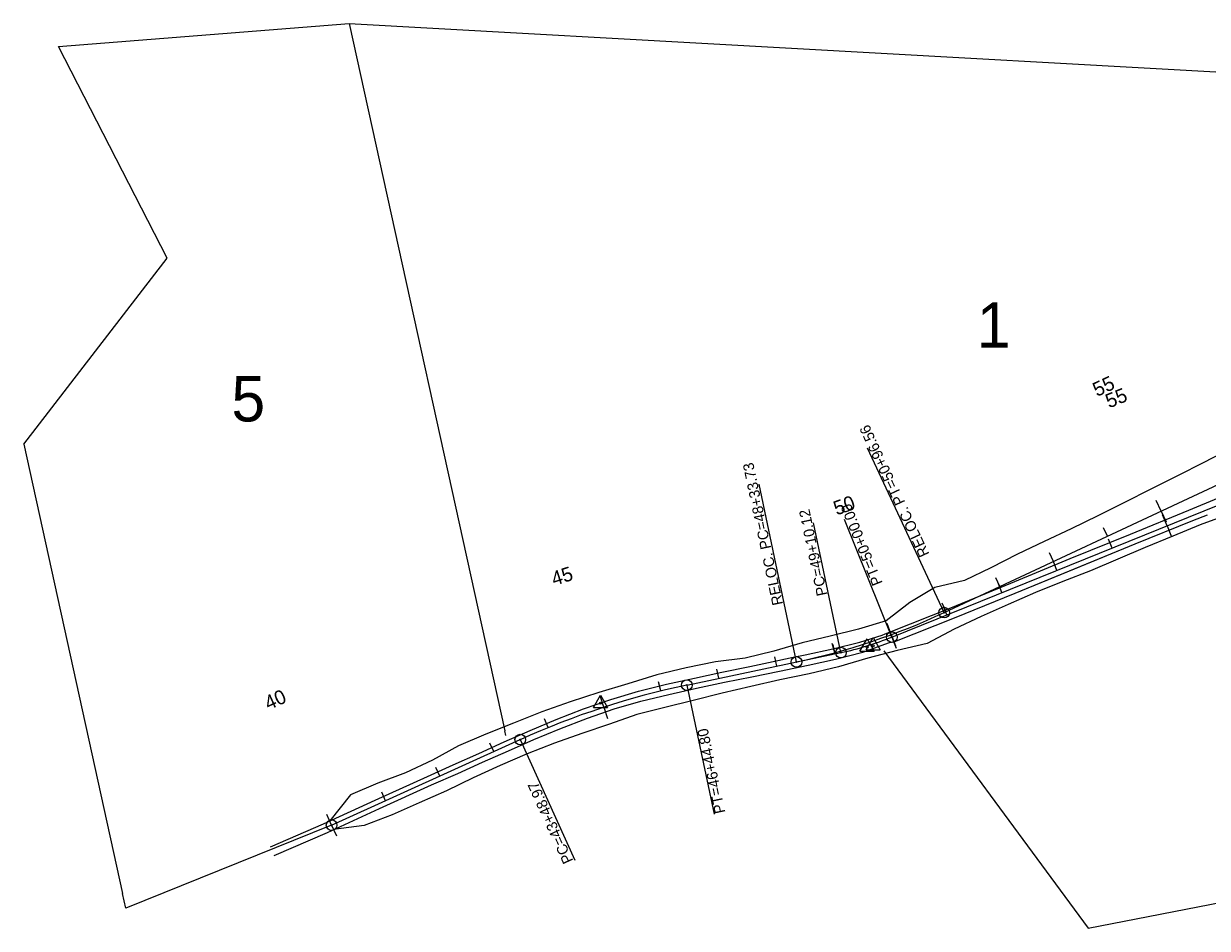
# Model space of a CAD drawing. Extents: x 1965308 to 1970456, y 1116335 to 1119906.
# Drawn here: x 1965308 to 1967302, y 1116957 to 1118481 of the extents above; entities that cross this region are included whole.
import ezdxf

# ---------------------------------------------------------------- set-up
doc = ezdxf.new("R2010")
doc.units = 0
for name, color, linetype in [('RD_EX_DV_Prop', 7, 'Continuous'), ('RD_EX_DV_TX_Prop', 7, 'Continuous'), ('RD_EX_Road', 7, 'Continuous'), ('RD_EX_RW', 7, 'Continuous'), ('RD_HC_Cl', 7, 'Continuous'), ('RD_HC_CL_Rel', 7, 'Continuous'), ('RD_HC_Data', 7, 'Continuous'), ('RD_HC_Data_Rel', 7, 'Continuous'), ('RD_HC_Data_Tic', 7, 'Continuous'), ('RD_HC_Data_Tic_Rel', 7, 'Continuous'), ('RD_HC_TX_Rel_Sta50', 7, 'Continuous'), ('RD_HC_TX_StaOther', 7, 'Continuous'), ('RD_PD_RW', 7, 'Continuous'), ('RD_SMD_Locator', 7, 'Continuous')]:
    doc.layers.add(name, color=color, linetype=linetype)

msp = doc.modelspace()

# ---------------------------------------------------------------- linework, layer by layer
at = {"layer": 'RD_EX_DV_Prop'}
for p, q in [((1965366.5, 1118442.8), (1965856.7, 1118481.4)), ((1965856.7, 1118481.4), (1967851.7, 1118370.2)), ((1965856.7, 1118481.4), (1966118.5, 1117290.2)), ((1965550, 1118086.1), (1965366.5, 1118442.8)), ((1965308.1, 1117773.1), (1965550, 1118086.1)), ((1965308.1, 1117773.1), (1965474.5, 1117016.1)), ((1966757.3, 1117425.1), (1967101.3, 1116957.5)), ((1966120.2, 1117282.5), (1966118.5, 1117290.2)), ((1965826.9, 1117131.2), (1965479.9, 1116991.6)), ((1965479.9, 1116991.6), (1965474.5, 1117016.1)), ((1967101.3, 1116957.5), (1967409.3, 1117017.8))]:
    msp.add_line(p, q, dxfattribs=at)
at = {"layer": 'RD_EX_Road'}
for points in [[(1966769.5, 1117457.5), (1966870.2, 1117497.3), (1966971.2, 1117539), (1967071.1, 1117580.2), (1967172.6, 1117621.5), (1967270.8, 1117661.7), (1967321.1, 1117682.6), (1967371.5, 1117702.9), (1967470.3, 1117741.6), (1967566.7, 1117779.5), (1967661.2, 1117817.5), (1967694.4, 1117831.2)], [(1966775.8, 1117440.6), (1966876.2, 1117480.4), (1966978.5, 1117522.1), (1967078.3, 1117563.1), (1967180.7, 1117605.1), (1967278, 1117644.7), (1967302.2, 1117654.1)], [(1965723.8, 1117094.5), (1965813.3, 1117133.7), (1965900.5, 1117173.5), (1965988.5, 1117213.4), (1966031.8, 1117233), (1966074.7, 1117252.1), (1966117.8, 1117271.6), (1966161.1, 1117290.5), (1966205.4, 1117309.2), (1966251.2, 1117327.4), (1966297.2, 1117343.1), (1966344.1, 1117357), (1966390.8, 1117368.6), (1966438.1, 1117379.1), (1966484.5, 1117389.1), (1966531.2, 1117398.7), (1966578.4, 1117408.6), (1966604.5, 1117414.1), (1966624.5, 1117418.3), (1966671.3, 1117428.3), (1966716.5, 1117439.3), (1966736.6, 1117445.6), (1966754.1, 1117451.4), (1966759.7, 1117453.5), (1966769.5, 1117457.5)], [(1965730, 1117080.3), (1965819.8, 1117119.1), (1965907.7, 1117159.3), (1965995.4, 1117199), (1966039.3, 1117218.5), (1966081.2, 1117237.1), (1966124.7, 1117256.6), (1966167.7, 1117275.6), (1966211.5, 1117293.6), (1966257.8, 1117311.6), (1966302.7, 1117327.2), (1966347.9, 1117340), (1966394.8, 1117351.6), (1966441.6, 1117361.9), (1966488.6, 1117372.1), (1966534.9, 1117381.3), (1966581.2, 1117390.9), (1966629.5, 1117400.9), (1966675.6, 1117411.1), (1966721.7, 1117422.8), (1966766.8, 1117439), (1966775.8, 1117440.6)]]:
    msp.add_lwpolyline(points, dxfattribs=at)
at = {"layer": 'RD_EX_RW'}
for points in [[(1966769.5, 1117457.5), (1966870.2, 1117497.3), (1966971.2, 1117539), (1967071.1, 1117580.2), (1967172.6, 1117621.5), (1967270.8, 1117661.7), (1967321.1, 1117682.6), (1967371.5, 1117702.9), (1967470.3, 1117741.6), (1967566.7, 1117779.5), (1967661.2, 1117817.5), (1967694.6, 1117831.3)], [(1966775.8, 1117440.6), (1966876.2, 1117480.4), (1966978.5, 1117522.1), (1967180.7, 1117605.1), (1967278, 1117644.7), (1967302.2, 1117654.1)], [(1965723.8, 1117094.5), (1965813.3, 1117133.7), (1965900.5, 1117173.5), (1965988.5, 1117213.4), (1966031.8, 1117233), (1966074.7, 1117252.1), (1966117.8, 1117271.6), (1966161.1, 1117290.5), (1966205.4, 1117309.2), (1966251.2, 1117327.4), (1966297.2, 1117343.1), (1966344.1, 1117357), (1966390.8, 1117368.6), (1966438.1, 1117379.1), (1966484.5, 1117389.1), (1966531.2, 1117398.7), (1966578.4, 1117408.6), (1966604.5, 1117414.1), (1966624.5, 1117418.3), (1966671.3, 1117428.3), (1966716.5, 1117439.3), (1966736.6, 1117445.6), (1966754.1, 1117451.4), (1966759.7, 1117453.5), (1966769.5, 1117457.5)], [(1965730, 1117080.3), (1965819.8, 1117119.1), (1965907.7, 1117159.3), (1965995.4, 1117199), (1966039.3, 1117218.5), (1966081.2, 1117237.1), (1966124.7, 1117256.6), (1966167.7, 1117275.6), (1966211.5, 1117293.6), (1966257.8, 1117311.6), (1966302.7, 1117327.2), (1966347.9, 1117340), (1966394.8, 1117351.6), (1966441.6, 1117361.9), (1966488.6, 1117372.1), (1966534.9, 1117381.3), (1966581.2, 1117390.9), (1966629.5, 1117400.9), (1966675.6, 1117411.1), (1966721.7, 1117422.8), (1966766.8, 1117439), (1966775.8, 1117440.6)]]:
    msp.add_lwpolyline(points, dxfattribs=at)
at = {"layer": 'RD_HC_Cl'}
for p, q in [((1966770.7, 1117448.1), (1967849.5, 1117883.9)), ((1966425.3, 1117367.2), (1966684.9, 1117421.9)), ((1965826.9, 1117131.2), (1966144.7, 1117275.3))]:
    msp.add_line(p, q, dxfattribs=at)
for centre, radius, start, end in [((1966579.6, 1117921.3), 510.3, 281.9047, 291.9958), ((1966705.5, 1116038), 1358.4, 101.9047, 114.3826)]:
    msp.add_arc(centre, radius, start, end, dxfattribs=at)
at = {"layer": 'RD_HC_CL_Rel'}
msp.add_line((1966858.9, 1117489.3), (1967685.7, 1117875.7), dxfattribs=at)
msp.add_arc((1966373.7, 1118527.5), 1145.9, 281.9047, 295.0463, dxfattribs=at)
at = {"layer": 'RD_HC_Data'}
for p, q in [((1966684.9, 1117421.9), (1966638.8, 1117640.3)), ((1966770.7, 1117448.1), (1966690.8, 1117646)), ((1966717, 1117424.4), (1966729, 1117445)), ((1966729, 1117445), (1966740.9, 1117424.4)), ((1966717, 1117424.4), (1966740.9, 1117424.4)), ((1966425.3, 1117367.2), (1966471.1, 1117149.9)), ((1966268, 1117329.7), (1966280, 1117350.3)), ((1966280, 1117350.3), (1966291.9, 1117329.7)), ((1966268, 1117329.7), (1966291.9, 1117329.7)), ((1966144.7, 1117275.3), (1966236.8, 1117072.1))]:
    msp.add_line(p, q, dxfattribs=at)
for centre, radius in [((1966770.7, 1117448.1), 9), ((1966770.7, 1117448.1), 9), ((1966684.9, 1117421.9), 9), ((1966729, 1117431.2), 1.59), ((1966770.7, 1117448.1), 0.845), ((1966770.7, 1117448.1), 0.845), ((1966684.9, 1117421.9), 0.845), ((1966425.3, 1117367.2), 9), ((1966425.3, 1117367.2), 0.845), ((1966280, 1117336.6), 1.59), ((1966144.7, 1117275.3), 9), ((1966144.7, 1117275.3), 0.845), ((1965826.9, 1117131.2), 9), ((1965826.9, 1117131.2), 0.845)]:
    msp.add_circle(centre, radius, dxfattribs=at)
at = {"layer": 'RD_HC_Data_Rel'}
for p, q in [((1966858.9, 1117489.3), (1966729.5, 1117766.2)), ((1966610.1, 1117406.2), (1966547, 1117705.5)), ((1966727.4, 1117426.5), (1966739.3, 1117447.2)), ((1966739.3, 1117447.2), (1966751.2, 1117426.5)), ((1966727.4, 1117426.5), (1966751.2, 1117426.5))]:
    msp.add_line(p, q, dxfattribs=at)
for centre, radius in [((1966858.9, 1117489.3), 9), ((1966858.9, 1117489.3), 0.845), ((1966739.3, 1117433.4), 1.59), ((1966610.1, 1117406.2), 9), ((1966610.1, 1117406.2), 0.845)]:
    msp.add_circle(centre, radius, dxfattribs=at)
at = {"layer": 'RD_HC_Data_Tic'}
for p, q in [((1967234.3, 1117635.4), (1967226.9, 1117653.9)), ((1967234.3, 1117635.4), (1967241.8, 1117616.8)), ((1967141.6, 1117597.9), (1967135.6, 1117612.8)), ((1967048.9, 1117560.5), (1967042.9, 1117575.3)), ((1966956.2, 1117523), (1966950.2, 1117537.9)), ((1966863.5, 1117485.6), (1966857.5, 1117500.4)), ((1966770.7, 1117448.1), (1966763.2, 1117466.7)), ((1966675, 1117419.9), (1966671.7, 1117435.5)), ((1966770.7, 1117448.1), (1966778.2, 1117429.6)), ((1966577.1, 1117399.2), (1966573.8, 1117414.9)), ((1966479.3, 1117378.6), (1966476, 1117394.3)), ((1966381.6, 1117357.3), (1966377.8, 1117372.8)), ((1966285.4, 1117329.9), (1966279.3, 1117348.9)), ((1966285.4, 1117329.9), (1966291.6, 1117310.8)), ((1966191.6, 1117295.5), (1966185.5, 1117310.3)), ((1966100.1, 1117255.1), (1966093.5, 1117269.6)), ((1966009, 1117213.8), (1966002.4, 1117228.3)), ((1965917.9, 1117172.5), (1965911.3, 1117187.1)), ((1965826.9, 1117131.2), (1965818.6, 1117149.4)), ((1965826.9, 1117131.2), (1965835.1, 1117113))]:
    msp.add_line(p, q, dxfattribs=at)
at = {"layer": 'RD_HC_Data_Tic_Rel'}
for p, q in [((1967224.4, 1117660.1), (1967215.9, 1117678.2)), ((1967224.4, 1117660.1), (1967232.8, 1117642)), ((1967133.8, 1117617.8), (1967127, 1117632.3)), ((1967043.2, 1117575.4), (1967036.4, 1117589.9)), ((1966952.6, 1117533.1), (1966945.8, 1117547.6)), ((1966862, 1117490.8), (1966855.2, 1117505.2)), ((1966769.8, 1117452.2), (1966762.9, 1117470.9)), ((1966769.8, 1117452.2), (1966776.7, 1117433.4)), ((1966674.5, 1117421.7), (1966670.3, 1117437.2))]:
    msp.add_line(p, q, dxfattribs=at)
at = {"layer": 'RD_PD_RW'}
for p, q in [((1967340.9, 1117765), (1967296.4, 1117742.1)), ((1967296.4, 1117742.1), (1967251.7, 1117719.7)), ((1967251.7, 1117719.7), (1967207.1, 1117697.1)), ((1967207.1, 1117697.1), (1967162.4, 1117674.5)), ((1967162.4, 1117674.5), (1967117.5, 1117652.5)), ((1967117.5, 1117652.5), (1967072.6, 1117630.4)), ((1967337.6, 1117654.3), (1967290.1, 1117637.3)), ((1967072.6, 1117630.4), (1967027.5, 1117609)), ((1967290.1, 1117637.3), (1967243.8, 1117618.3)), ((1967243.8, 1117618.3), (1967197.6, 1117599.1)), ((1967027.5, 1117609), (1966982.2, 1117587.8)), ((1967197.6, 1117599.1), (1967151.6, 1117579.5)), ((1966982.2, 1117587.8), (1966937.7, 1117564.8)), ((1967151.6, 1117579.5), (1967105.6, 1117559.8)), ((1966937.7, 1117564.8), (1966892.8, 1117543.2)), ((1967105.6, 1117559.8), (1967058.8, 1117541.9)), ((1966842.9, 1117531.7), (1966801.1, 1117506.3)), ((1966892.8, 1117543.2), (1966842.9, 1117531.7)), ((1967058.8, 1117541.9), (1967012.5, 1117522.9)), ((1967012.5, 1117522.9), (1966966.7, 1117502.9)), ((1966801.1, 1117506.3), (1966761, 1117475.6)), ((1966966.7, 1117502.9), (1966920.9, 1117482.7)), ((1966761, 1117475.6), (1966714.3, 1117461.6)), ((1966920.9, 1117482.7), (1966875.7, 1117461.6)), ((1966714.3, 1117461.6), (1966666.9, 1117449.8)), ((1966875.7, 1117461.6), (1966830.2, 1117437.3)), ((1966619.5, 1117438.3), (1966571.8, 1117424.1)), ((1966666.9, 1117449.8), (1966619.5, 1117438.3)), ((1966830.2, 1117437.3), (1966779.4, 1117425.6)), ((1966523.3, 1117412.5), (1966473.5, 1117406.2)), ((1966571.8, 1117424.1), (1966523.3, 1117412.5)), ((1966730, 1117412.4), (1966680.9, 1117398.2)), ((1966779.4, 1117425.6), (1966730, 1117412.4)), ((1966424.4, 1117396.5), (1966374.9, 1117384.3)), ((1966473.5, 1117406.2), (1966424.4, 1117396.5)), ((1966680.9, 1117398.2), (1966631.4, 1117386)), ((1966374.9, 1117384.3), (1966326.1, 1117369.4)), ((1966582.1, 1117375.9), (1966533.3, 1117365)), ((1966631.4, 1117386), (1966582.1, 1117375.9)), ((1966277.3, 1117354.8), (1966228.8, 1117339.1)), ((1966326.1, 1117369.4), (1966277.3, 1117354.8)), ((1966484.6, 1117353.4), (1966436.1, 1117341.4)), ((1966533.3, 1117365), (1966484.6, 1117353.4)), ((1966228.8, 1117339.1), (1966180.8, 1117321.9)), ((1966436.1, 1117341.4), (1966388.5, 1117329.3)), ((1966180.8, 1117321.9), (1966133.4, 1117302.8)), ((1966340.9, 1117317.6), (1966294.8, 1117301.1)), ((1966388.5, 1117329.3), (1966340.9, 1117317.6)), ((1966133.4, 1117302.8), (1966086.7, 1117284.8)), ((1966294.8, 1117301.1), (1966248.3, 1117285.8)), ((1966086.7, 1117284.8), (1966040.6, 1117265.1)), ((1966248.3, 1117285.8), (1966202.1, 1117269.5)), ((1966040.6, 1117265.1), (1965996.7, 1117240.8)), ((1966156.5, 1117251.5), (1966110.7, 1117231.6)), ((1966202.1, 1117269.5), (1966156.5, 1117251.5)), ((1965996.7, 1117240.8), (1965951.6, 1117219.5)), ((1966110.7, 1117231.6), (1966065.3, 1117210.7)), ((1965951.6, 1117219.5), (1965904.7, 1117201.9)), ((1965904.7, 1117201.9), (1965858.4, 1117182.2)), ((1966065.3, 1117210.7), (1966020.2, 1117189.2)), ((1965858.4, 1117182.2), (1965823.6, 1117138.4)), ((1966020.2, 1117189.2), (1965974.5, 1117168.9)), ((1965974.5, 1117168.9), (1965928.6, 1117148.8)), ((1965928.6, 1117148.8), (1965881.8, 1117130.7)), ((1965881.8, 1117130.7), (1965830.2, 1117123.9))]:
    msp.add_line(p, q, dxfattribs=at)
at = {"layer": 'RD_SMD_Locator'}
for centre in [(1966729, 1117431.2), (1966770.7, 1117448.1), (1966770.7, 1117448.1), (1966684.9, 1117421.9), (1966425.3, 1117367.2), (1966280, 1117336.6), (1966144.7, 1117275.3), (1965826.9, 1117131.2)]:
    msp.add_circle(centre, 0.003, dxfattribs=at)

# ---------------------------------------------------------------- texts
at = {"layer": 'RD_EX_DV_TX_Prop'}
for s, p in [('1', (1966913.8, 1117935.5)), ('5', (1965658.1, 1117811.3))]:
    msp.add_text(s, height=76.4, dxfattribs=at).set_placement(p)
at = {"layer": 'RD_HC_Data'}
for s, rotation, p in [('PT=50+00.00', 111.9958, (1966755.4, 1117539.2)), ('PC=49+10.12', 101.9047, (1966662.3, 1117519.4)), ('PT=46+44.80', 101.9047, (1966490.3, 1117152.8)), ('PC=43+48.97', 114.3826, (1966234.3, 1117071.3))]:
    msp.add_text(s, height=18, rotation=rotation, dxfattribs=at).set_placement(p)
at = {"layer": 'RD_HC_Data_Rel'}
for s, rotation, p in [('RELOC. PT=50+96.56', 115.0463, (1966834.3, 1117588)), ('RELOC. PC=48+33.73', 101.9047, (1966587.5, 1117503.6))]:
    msp.add_text(s, height=18, rotation=rotation, dxfattribs=at).set_placement(p)
at = {"layer": 'RD_HC_TX_Rel_Sta50'}
for s, rotation, p in [('55', 25.0463, (1967116.2, 1117852.4)), ('50', 20.2184, (1966677.7, 1117652.7))]:
    msp.add_text(s, height=24, rotation=rotation, dxfattribs=at).set_placement(p)
at = {"layer": 'RD_HC_TX_StaOther'}
for s, rotation, p in [('55', 21.9958, (1967136.6, 1117833.2)), ('45', 18.0122, (1966201.7, 1117534)), ('40', 24.3826, (1965720.5, 1117324.5))]:
    msp.add_text(s, height=24, rotation=rotation, dxfattribs=at).set_placement(p)

doc.saveas('drawing.dxf')
